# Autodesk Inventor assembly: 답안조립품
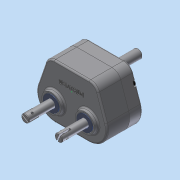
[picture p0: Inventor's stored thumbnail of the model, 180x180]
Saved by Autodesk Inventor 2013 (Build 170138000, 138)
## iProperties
Created: 2014-12
Part Number: 답안조립품
Document SubType Name: Assembly
Designer: Administrator
Author: Administrator
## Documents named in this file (14)
- C:\Users\Administrator\Desktop\441209V1031\441209V1031\답안조립품.iam
- C:\Users\Administrator\Desktop\441209V1031\441209V1031\본체.ipt
- C:\Users\Administrator\Desktop\441209V1031\441209V1031\M 5 x 35.ipt
- C:\Users\Administrator\Desktop\441209V1031\441209V1031\멈춤링.ipt
- C:\Users\Administrator\Desktop\441209V1031\441209V1031\메인기어.ipt
- C:\Users\Administrator\Desktop\441209V1031\441209V1031\메인축.ipt
- C:\Users\Administrator\Desktop\441209V1031\441209V1031\베어링- 6202.ipt
- C:\Users\Administrator\Desktop\441209V1031\441209V1031\베어링- 6203.ipt
- C:\Users\Administrator\Desktop\441209V1031\441209V1031\서브기어.ipt
- C:\Users\Administrator\Desktop\441209V1031\441209V1031\서브축.ipt
- C:\Users\Administrator\Desktop\441209V1031\441209V1031\오일시일-D-15.ipt
- C:\Users\Administrator\Desktop\441209V1031\441209V1031\오일시일-D-17.ipt
- C:\Users\Administrator\Desktop\441209V1031\441209V1031\커버.ipt
- C:\Users\Administrator\Desktop\441209V1031\441209V1031\키5x5.ipt
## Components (13 placed, 6 different names)
1. KS B 1003 - 미터 M 5 x 35:1
2. KS B 1336 17 x 1:1
3. KS B 2023 6202 - 15 x 35 x 11:1
4. KS B 2023 6203 - 17 x 40 x 12:1
5. KS B 2804 D D - 15 30 7:1
6. KS B 2804 D D - 17 30 8:1
7. KS B 1336 17 x 1:2
8. KS B 1336 17 x 1:3
9. KS B 2023 6202 - 15 x 35 x 11:2
10. KS B 2804 D D - 17 30 8:2
11. KS B 2023 6203 - 17 x 40 x 12:2
12. KS B 1003 - 미터 M 5 x 35:3
13. KS B 1003 - 미터 M 5 x 35:4
